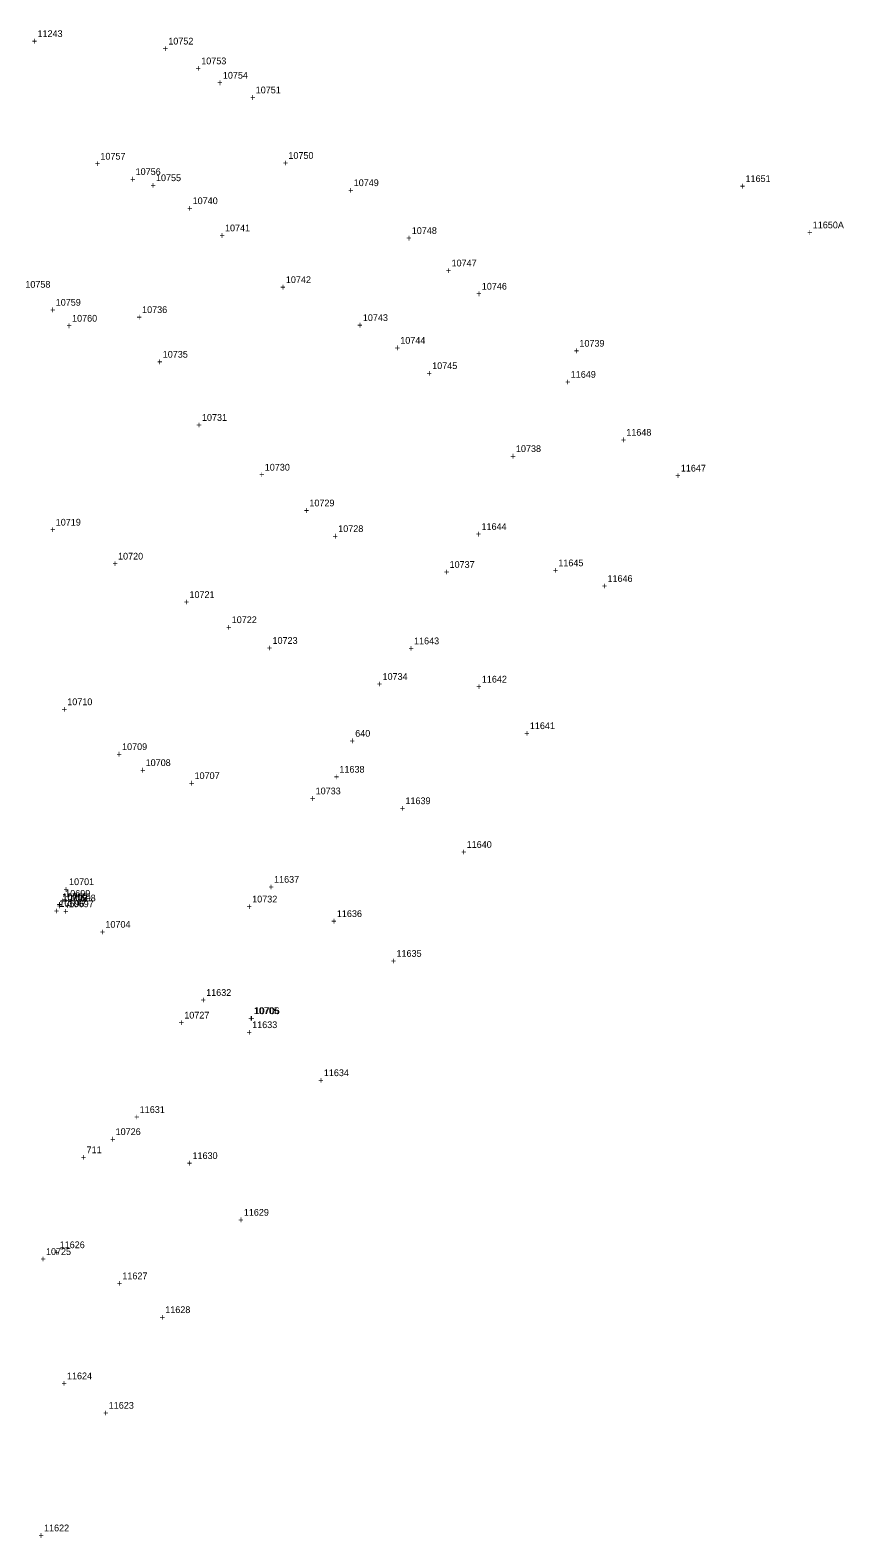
# Model space of a CAD drawing. Extents: x 1160051 to 1162814, y 614604 to 619560.
# Drawn here: x 1162513 to 1162814, y 618981 to 619540 of the extents above; entities that cross this region are included whole.
import ezdxf

# ---------------------------------------------------------------- set-up
doc = ezdxf.new("R2010")
doc.units = 0
for name, color, linetype in [('S_Control_Temp_Traverse', 7, 'Continuous'), ('S_Control_Traverse_Point', 7, 'Continuous'), ('S_Drainage_Culvert_Top', 7, 'Continuous'), ('S_Drainage_Invert', 7, 'Continuous'), ('S_Ground_Elevation', 7, 'Continuous'), ('S_Guardrail_Beam', 7, 'Continuous'), ('S_Traffic_Sign_DoublePost', 7, 'Continuous')]:
    doc.layers.add(name, color=color, linetype=linetype)

msp = doc.modelspace()

# ---------------------------------------------------------------- texts
at = {"layer": 'S_Control_Temp_Traverse'}
for s, p in [('640', (1162633.3, 619277.73)), ('+', (1162631.24, 619274.98))]:
    msp.add_text(s, height=2.5, dxfattribs=at).set_placement(p)
at = {"layer": 'S_Control_Traverse_Point'}
for s, p in [('711', (1162533.73, 619123.3)), ('711', (1162533.73, 619123.3)), ('+', (1162531.66, 619120.55)), ('+', (1162531.66, 619120.55))]:
    msp.add_text(s, height=2.5, dxfattribs=at).set_placement(p)
at = {"layer": 'S_Drainage_Culvert_Top'}
for s, p in [('10703', (1162524.84, 619216.5)), ('+', (1162522.78, 619213.75)), ('+', (1162593.65, 619172.13)), ('10705', (1162595.71, 619174.88))]:
    msp.add_text(s, height=2.5, dxfattribs=at).set_placement(p)
at = {"layer": 'S_Drainage_Invert'}
for s, p in [('10702', (1162524.81, 619216.95)), ('+', (1162522.75, 619214.2)), ('+', (1162593.96, 619172.1)), ('10706', (1162596.02, 619174.85))]:
    msp.add_text(s, height=2.5, dxfattribs=at).set_placement(p)
at = {"layer": 'S_Ground_Elevation'}
for s, p in [('11243', (1162515.54, 619537.17)), ('+', (1162513.48, 619534.42)), ('+', (1162561.95, 619531.64)), ('10752', (1162564.01, 619534.39)), ('+', (1162574.16, 619524.31)), ('10753', (1162576.23, 619527.06)), ('+', (1162582.19, 619518.98)), ('10754', (1162584.25, 619521.73)), ('+', (1162594.36, 619513.54)), ('10751', (1162596.42, 619516.29)), ('10757', (1162538.86, 619491.71)), ('10750', (1162608.53, 619491.99)), ('+', (1162536.8, 619488.96)), ('10756', (1162551.91, 619485.99)), ('+', (1162606.47, 619489.24)), ('+', (1162549.85, 619483.24)), ('+', (1162557.39, 619480.98)), ('10755', (1162559.45, 619483.73)), ('+', (1162630.67, 619479.13)), ('10749', (1162632.73, 619481.88)), ('10740', (1162573.04, 619475.2)), ('+', (1162570.98, 619472.45)), ('+', (1162582.96, 619462.37)), ('10741', (1162585.03, 619465.12)), ('10748', (1162654.26, 619464.14)), ('+', (1162652.2, 619461.39)), ('10747', (1162669.01, 619452.1)), ('10742', (1162607.6, 619445.95)), ('+', (1162666.95, 619449.35)), ('10758', (1162511.03, 619444.2)), ('+', (1162605.54, 619443.2)), ('+', (1162678.16, 619440.75)), ('10746', (1162680.22, 619443.5)), ('+', (1162520.22, 619434.78)), ('10759', (1162522.29, 619437.53)), ('10736', (1162554.31, 619434.83)), ('+', (1162526.29, 619428.88)), ('10760', (1162528.35, 619431.63)), ('+', (1162552.25, 619432.08)), ('+', (1162634.06, 619429.12)), ('10743', (1162636.13, 619431.87)), ('10744', (1162650, 619423.44)), ('10735', (1162561.96, 619418.27)), ('+', (1162647.94, 619420.69)), ('+', (1162559.9, 619415.52)), ('10745', (1162661.83, 619414.04)), ('+', (1162659.77, 619411.29)), ('+', (1162711.12, 619408.06)), ('11649', (1162713.18, 619410.81)), ('10731', (1162576.49, 619394.84)), ('+', (1162574.43, 619392.09)), ('11648', (1162733.77, 619389.33)), ('+', (1162731.71, 619386.58)), ('+', (1162597.71, 619373.65)), ('10730', (1162599.78, 619376.4)), ('+', (1162751.92, 619373.29)), ('11647', (1162753.98, 619376.04)), ('10729', (1162616.31, 619363.14)), ('10719', (1162522.3, 619356.01)), ('+', (1162614.25, 619360.39)), ('+', (1162520.24, 619353.26)), ('+', (1162624.94, 619350.87)), ('10728', (1162627, 619353.62)), ('+', (1162678.03, 619351.64)), ('11644', (1162680.1, 619354.39)), ('+', (1162543.32, 619340.66)), ('10720', (1162545.39, 619343.41)), ('11645', (1162708.57, 619340.93)), ('+', (1162706.51, 619338.18)), ('11646', (1162726.8, 619335.12)), ('10721', (1162571.87, 619329.18)), ('+', (1162724.74, 619332.37)), ('+', (1162569.81, 619326.43)), ('+', (1162585.47, 619317.1)), ('10722', (1162587.53, 619319.85)), ('10723', (1162602.65, 619312.15)), ('11643', (1162655.1, 619312.01)), ('+', (1162600.59, 619309.4)), ('+', (1162653.04, 619309.26)), ('+', (1162678.18, 619295.05)), ('11642', (1162680.24, 619297.8)), ('10710', (1162526.57, 619289.42)), ('+', (1162524.51, 619286.67)), ('11641', (1162698.03, 619280.55)), ('10709', (1162546.88, 619272.78)), ('+', (1162695.97, 619277.8)), ('+', (1162544.82, 619270.03)), ('10708', (1162555.62, 619266.84)), ('+', (1162553.56, 619264.09)), ('10707', (1162573.76, 619262.03)), ('+', (1162625.39, 619261.64)), ('11638', (1162627.45, 619264.39)), ('+', (1162571.7, 619259.28)), ('+', (1162649.86, 619249.97)), ('11639', (1162651.92, 619252.72)), ('+', (1162672.54, 619233.76)), ('11640', (1162674.6, 619236.51)), ('10701', (1162527.23, 619222.7)), ('11637', (1162603.22, 619223.57)), ('10700', (1162524.71, 619217.14)), ('+', (1162525.17, 619219.95)), ('10699', (1162525.82, 619218.38)), ('10698', (1162527.82, 619216.66)), ('+', (1162601.16, 619220.82)), ('+', (1162521.59, 619211.88)), ('+', (1162522.64, 619214.39)), ('10696', (1162523.65, 619214.63)), ('+', (1162523.76, 619215.63)), ('+', (1162525.02, 619211.75)), ('+', (1162525.76, 619213.91)), ('10697', (1162527.08, 619214.5)), ('11636', (1162626.5, 619210.87)), ('10704', (1162540.7, 619206.89)), ('+', (1162624.44, 619208.12)), ('+', (1162538.64, 619204.14)), ('11635', (1162648.61, 619196.11)), ('+', (1162646.55, 619193.36)), ('+', (1162576, 619178.87)), ('11632', (1162578.06, 619181.62)), ('+', (1162593.05, 619166.93)), ('11633', (1162595.11, 619169.68)), ('11634', (1162621.68, 619151.87)), ('+', (1162619.62, 619149.12)), ('11631', (1162553.44, 619138.23)), ('+', (1162551.38, 619135.48)), ('11630', (1162573, 619121.14)), ('+', (1162570.94, 619118.39)), ('11629', (1162592.01, 619100.12)), ('+', (1162589.94, 619097.37)), ('11626', (1162523.76, 619088.08)), ('+', (1162521.7, 619085.33)), ('11627', (1162547, 619076.56)), ('+', (1162544.94, 619073.81)), ('+', (1162560.83, 619061.26)), ('11628', (1162562.89, 619064.01)), ('11624', (1162526.46, 619039.47)), ('+', (1162524.4, 619036.72)), ('11623', (1162541.95, 619028.54)), ('+', (1162539.89, 619025.79)), ('11622', (1162517.97, 618983.1)), ('+', (1162515.91, 618980.35))]:
    msp.add_text(s, height=2.5, dxfattribs=at).set_placement(p)
at = {"layer": 'S_Guardrail_Beam'}
for s, p in [('+', (1162714.33, 619419.6)), ('10739', (1162716.39, 619422.35)), ('+', (1162690.81, 619380.53)), ('10738', (1162692.87, 619383.28)), ('10737', (1162668.27, 619340.32)), ('+', (1162666.21, 619337.57)), ('+', (1162641.37, 619296.04)), ('10734', (1162643.43, 619298.79)), ('10733', (1162618.62, 619256.37)), ('+', (1162616.55, 619253.62)), ('10732', (1162595.11, 619216.26)), ('+', (1162593.05, 619213.51)), ('10727', (1162569.94, 619173.22)), ('+', (1162567.88, 619170.47)), ('+', (1162542.44, 619127.27)), ('10726', (1162544.5, 619130.02)), ('+', (1162516.62, 619082.82)), ('10725', (1162518.68, 619085.57))]:
    msp.add_text(s, height=2.5, dxfattribs=at).set_placement(p)
at = {"layer": 'S_Traffic_Sign_DoublePost'}
for s, p in [('+', (1162775.9, 619480.66)), ('11651', (1162777.96, 619483.41)), ('+', (1162800.82, 619463.49)), ('11650A', (1162802.88, 619466.24))]:
    msp.add_text(s, height=2.5, dxfattribs=at).set_placement(p)

doc.saveas('drawing.dxf')
